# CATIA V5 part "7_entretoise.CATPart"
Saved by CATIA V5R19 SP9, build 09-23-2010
Part number: 7_entretoise
Revision: ANY
Definition: UNKNOWN
Nomenclature: 7_entretoise
Source: Unknown
Bounding box of the stored display mesh (mm): x -50 to 50, y 0 to 27, z -50 to 50
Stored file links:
  Y:\fin de projet cabestan poupee\7_entretoise.CATPart
  Ass_arbre poupee_1.CATProduct
  Y:\bricolage cabestan\6_axe.CATPart
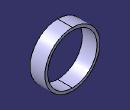
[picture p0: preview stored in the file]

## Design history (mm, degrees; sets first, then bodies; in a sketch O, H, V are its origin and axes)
Body1 "NONE" (main body)
  Solid1: solid without history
